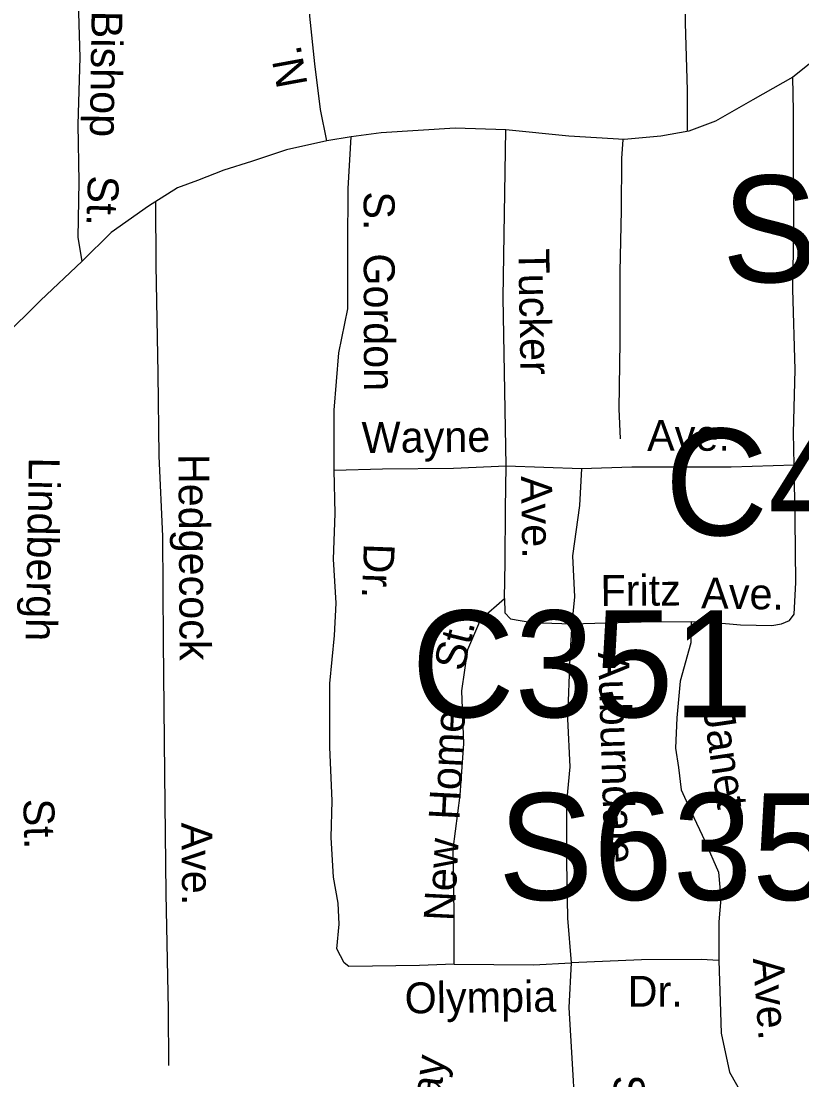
# Model space of a CAD drawing. Extents: x 1547597 to 1699558, y 810033 to 920809.
# Drawn here: x 1609660 to 1612059, y 851314 to 854570 of the extents above; entities that cross this region are included whole.
import ezdxf

# ---------------------------------------------------------------- set-up
doc = ezdxf.new("R2010")
doc.units = 0
for name, color, linetype in [('Exist Road Non-System Type 51', 7, 'Continuous'), ('Exist Road Non-System Type 51 Label', 7, 'Continuous'), ('Exist Road Primary Interstate Structure Ovrhead Sign Number Label', 7, 'Continuous'), ('Exist Road Secondary Structure Culvert Number Label', 7, 'Continuous'), ('Exist Road Secondary Type 51 Attributed', 7, 'Continuous')]:
    doc.layers.add(name, color=color, linetype=linetype)

msp = doc.modelspace()

# ---------------------------------------------------------------- linework, layer by layer
at = {"layer": 'Exist Road Non-System Type 51'}
msp.add_line((1611150.2, 853202.2), (1611381.8, 853193.9), dxfattribs=at)
for points in [[(1611707, 854229.9), (1611707, 854357.3), (1611700.7, 854563.4), (1611699.1, 854691.3), (1611696.3, 854747.4), (1611688.6, 854765.3), (1611668.9, 854779.7), (1611637.1, 854790.4), (1611457.1, 854785.6), (1611321.2, 854784.2)], [(1610599.2, 854201.9), (1610579.1, 854298.2), (1610561.8, 854438.4), (1610546.3, 854584.6), (1610536.9, 854722.7)], [(1609847.4, 853831.3), (1609834.6, 853904), (1609837.6, 854075.9), (1609835, 854251.8), (1609840.8, 854457.6), (1609837.4, 854595.6), (1609834.3, 854651.7)], [(1612035.4, 853205.8), (1612033.2, 853303.9), (1612038.7, 853497.7), (1612031.3, 853745.6), (1612034.6, 853925.4), (1612032.8, 854153.4), (1612033.4, 854293.3), (1612031.3, 854397.4)], [(1610621.1, 853189.3), (1610621.1, 853373.3), (1610635.6, 853550.1), (1610663.6, 853684.9), (1610663.2, 853876.8), (1610664.5, 854054.7), (1610673.5, 854214.4)], [(1611150.2, 853202.2), (1611140.9, 853720.2), (1611149.4, 854235.6)], [(1611501.3, 853285.7), (1611497, 853377.6), (1611500.9, 853583.5), (1611500.9, 853799.4), (1611504.3, 853987.2), (1611505.4, 854147.1), (1611510.1, 854205.9)], [(1610113.1, 851358.4), (1610112.4, 851530.3), (1610105, 851886.2), (1610101.7, 852256.1), (1610097.3, 852661.8), (1610095.3, 852985.8), (1610083.9, 853231.8), (1610080.6, 853485.8), (1610074.8, 853819.7), (1610073.8, 854015.3)], [(1611381.8, 853193.9), (1611535.8, 853199.1), (1611841.3, 853199.5), (1612035.4, 853205.8)], [(1611718.6, 852724), (1611790.6, 852720.7), (1611870.3, 852713.1), (1611966.3, 852711.3), (1611996.2, 852716.9), (1612020.4, 852726.5), (1612034.9, 852746.2), (1612040.6, 852843.9), (1612038.2, 853037.9), (1612035.4, 853205.8)], [(1610990.8, 851670.2), (1610883.9, 851665.9), (1610666.2, 851663), (1610651.8, 851673.8), (1610630.2, 851717.1), (1610637.4, 851792.9), (1610633.8, 851857.8), (1610619.3, 851937.2), (1610612.1, 852059.9), (1610615.7, 852171.7), (1610608.5, 852337.7), (1610608.5, 852532.6), (1610623, 852680.5), (1610628, 852780), (1610619.3, 852915), (1610624.8, 853055.8), (1610621.1, 853189.3)], [(1610621.1, 853189.3), (1610770.4, 853193.3), (1610988.2, 853195.2), (1611150.2, 853202.2)], [(1611144.6, 852794.5), (1611146.6, 852906.5), (1611147.8, 853070.3), (1611150.2, 853202.2)], [(1611381.8, 853193.9), (1611375.7, 853080.1), (1611354.3, 852925.1), (1611360.1, 852799.1), (1611351.4, 852716.6)], [(1610990.8, 851670.2), (1610990.8, 851825.3), (1610987.2, 852023.8), (1611008.8, 852189.8), (1611019.6, 852348.5), (1611014.2, 852510.9), (1611032.2, 852637.2), (1611071.9, 852731), (1611144.6, 852794.5)], [(1611144.6, 852794.5), (1611145.9, 852750.6), (1611163.5, 852732.2), (1611229.1, 852720.9), (1611351.4, 852716.6)], [(1611351.4, 852716.6), (1611346, 852615.5), (1611338.7, 852424.3), (1611346, 852276.4), (1611335.1, 852168.1), (1611335.1, 851984.1), (1611338.7, 851810.9), (1611349.6, 851673.8)], [(1611351.4, 852716.6), (1611564.9, 852722.9), (1611718.6, 852724)], [(1611718.6, 852724), (1611717.5, 852658), (1611684.9, 852539.8), (1611674.1, 852427.9), (1611670.4, 852334.3), (1611679.2, 852274.3), (1611688.2, 852206.3), (1611718.8, 852137.9), (1611760.6, 852049.1), (1611802.7, 851952.5), (1611809.3, 851872.3), (1611803.9, 851800.1), (1611803.9, 851681)], [(1610990.8, 851670.2), (1611233.8, 851667.4), (1611349.6, 851673.8)], [(1611349.6, 851673.8), (1611342.3, 851536.7), (1611353.2, 851363.5), (1611360.4, 851240.8), (1611371.2, 851118.1), (1611374.8, 851056.8)], [(1611803.9, 851681), (1611749.4, 851684), (1611565.7, 851683.3), (1611349.6, 851673.8)], [(1611803.9, 851681), (1611807.5, 851554.7), (1611811.1, 851457.3), (1611836.4, 851338.2), (1611883.2, 851255.3)]]:
    msp.add_lwpolyline(points, dxfattribs=at)
at = {"layer": 'Exist Road Secondary Type 51 Attributed'}
msp.add_lwpolyline([(1612320.2, 854629.1), (1612186.9, 854521.7), (1612031.3, 854397.4), (1611908.3, 854327.6), (1611792.9, 854262.2), (1611711.5, 854231.7), (1611625.1, 854216.4), (1611513.2, 854206.2), (1611342.9, 854216.4), (1611149.4, 854235.6), (1610993.6, 854240.5), (1610765.6, 854226.7), (1610673.5, 854214.4), (1610599.2, 854201.9), (1610475, 854174.2), (1610367.2, 854138.3), (1610282.4, 854111.2), (1610201.5, 854079.9), (1610139.8, 854057.1), (1610051.3, 854001.1), (1609935.8, 853919.8), (1609847.4, 853831.3), (1609719.3, 853710.3), (1609601.9, 853594.7)], dxfattribs=at)

# ---------------------------------------------------------------- texts
at = {"layer": 'Exist Road Non-System Type 51 Label'}
for s, rotation, p in [('Bishop', 269.2178, (1609876.2, 854602.2)), ('N.', 100.3376, (1610540.2, 854374.9)), ('St.', 267.9764, (1609865.4, 854096.4)), ('S.  Gordon', 270.0921, (1610712.2, 854046.2)), ('Tucker', 271.0285, (1611187.5, 853869.8)), ('Wayne', 0.5222, (1610706.4, 853241.9)), ('Ave.', 0.0757, (1611583.4, 853248.4)), ('Lindbergh', 268.9663, (1609683.5, 853228.9)), ('Hedgecock', 270.3591, (1610142.9, 853238.8)), ('Ave.', 270.9296, (1611195.8, 853170.5)), ('Dr.', 267.8801, (1610713, 852964.8)), ('Fritz', 0.4036, (1611440.2, 852771.2)), ('Ave.', 358.9586, (1611748.9, 852764.5)), ('St.', 76.3877, (1611019.2, 852567.5)), ('Auburndale', 271.8096, (1611432.5, 852628)), ('Home', 87.0099, (1611006.6, 852111.8)), ('Janet', 278.3322, (1611755.6, 852450.5)), ('St.', 271.5702, (1609666, 852177.8)), ('Ave.', 270.5113, (1610152.2, 852105.1)), ('New', 87.1116, (1610991.3, 851800.8)), ('Ave.', 274.1445, (1611908.2, 851687.2)), ('Olympia', 0.7095, (1610838.6, 851518.3)), ('Dr.', 0.2108, (1611523.6, 851538.9)), ('Creekway', 82.8364, (1610893.9, 850823.9)), ('St.', 274.4465, (1611477.6, 851325.7))]:
    msp.add_text(s, height=95, rotation=rotation, dxfattribs=at).set_placement(p)
at = {"layer": 'Exist Road Primary Interstate Structure Ovrhead Sign Number Label'}
for s, p in [('S633', (1611813.3, 853767)), ('S635', (1611125.4, 851867.4))]:
    msp.add_text(s, height=328.08, dxfattribs=at).set_placement(p)
at = {"layer": 'Exist Road Secondary Structure Culvert Number Label'}
for s, p in [('C411', (1611637.8, 852988.6)), ('C351', (1610859.2, 852429.4))]:
    msp.add_text(s, height=328.08, dxfattribs=at).set_placement(p)

doc.saveas('drawing.dxf')
